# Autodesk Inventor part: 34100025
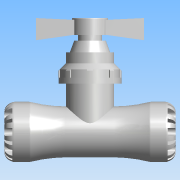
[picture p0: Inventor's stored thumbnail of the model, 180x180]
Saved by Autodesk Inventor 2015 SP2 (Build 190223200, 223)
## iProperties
Created: 2016-12
Part Number: 34100025
Material: PVC-Piping
Description: Plasson COMPRESSION STOPTAP 25 SERIES 1
Document SubType Name: Modeling
Designer: KIM
Mass: 61.7504 g
Surface Area: 140.097 cm^2
Volume: 44.1074 cm^3
Density: 1.4 g/cm^3
Appearance: Smooth - White
Author: KIM
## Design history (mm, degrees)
derived "03410.ipt"
feature "Solid1::03410.ipt"
feature "Solid2::03410.ipt"
tag "TaggingFeature1"
body "Solid1"
other parameters: "d1" = 20.16, "d2" = 25, "d3" = 31.25, "d4" = 47, "d6" = 48, "d8" = 39.95, "d13" = 6.3, "d14" = 6.3, "d15" = 0, "d17" = 360 deg, "d19" = 8 deg, "d20" = 0.5, "d21" = 0.5, "d22" = 8 deg, "d24" = 0, "d26" = 360 deg, "d33" = 4.7, "d35" = 3.125, "d65" = 0.47, "d69" = 134, "d71" = 25, "d72" = 47, "d73" = 31.25, "d74" = 20.16, "d75" = 67, "d76" = 3.125, "d77" = 48, "d80" = 6.3, "d82" = 6.3, "d83" = 0, "d85" = 360 deg, "d92" = 0, "d94" = 360 deg, "d96" = 89, "d97" = 47, "d98" = 37.6, "d99" = 37.6, "d100" = 135 deg, "d101" = 18.8, "d102" = 70 deg, "d103" = 48.95, "d104" = 71.2, "d105" = 62.3, "d107" = 75.65, "d108" = 84.6, "d110" = 12.015, "d111" = 4.005, "d112" = 14.1, "d113" = 0, "d114" = 49.35, "d115" = 4.7, "d116" = 0, "d117" = 4.7, "d119" = 0, "d121" = 360 deg, "d126" = 0.5, "d127" = 0.5, "d128" = 8 deg, "d129" = 8 deg, "d130" = 0.47, "d132" = 0, "d_" = 25, "E_" = 47, "H_" = 134, "l_" = 48, "A_" = 89, "l_1" = 48, "E_1" = 47, "d9" = 7.875, "d11" = 47, "d12" = 31.25, "d78" = 47, "d79" = 31.25, "d81" = 7.875, "d109" = 13.35
